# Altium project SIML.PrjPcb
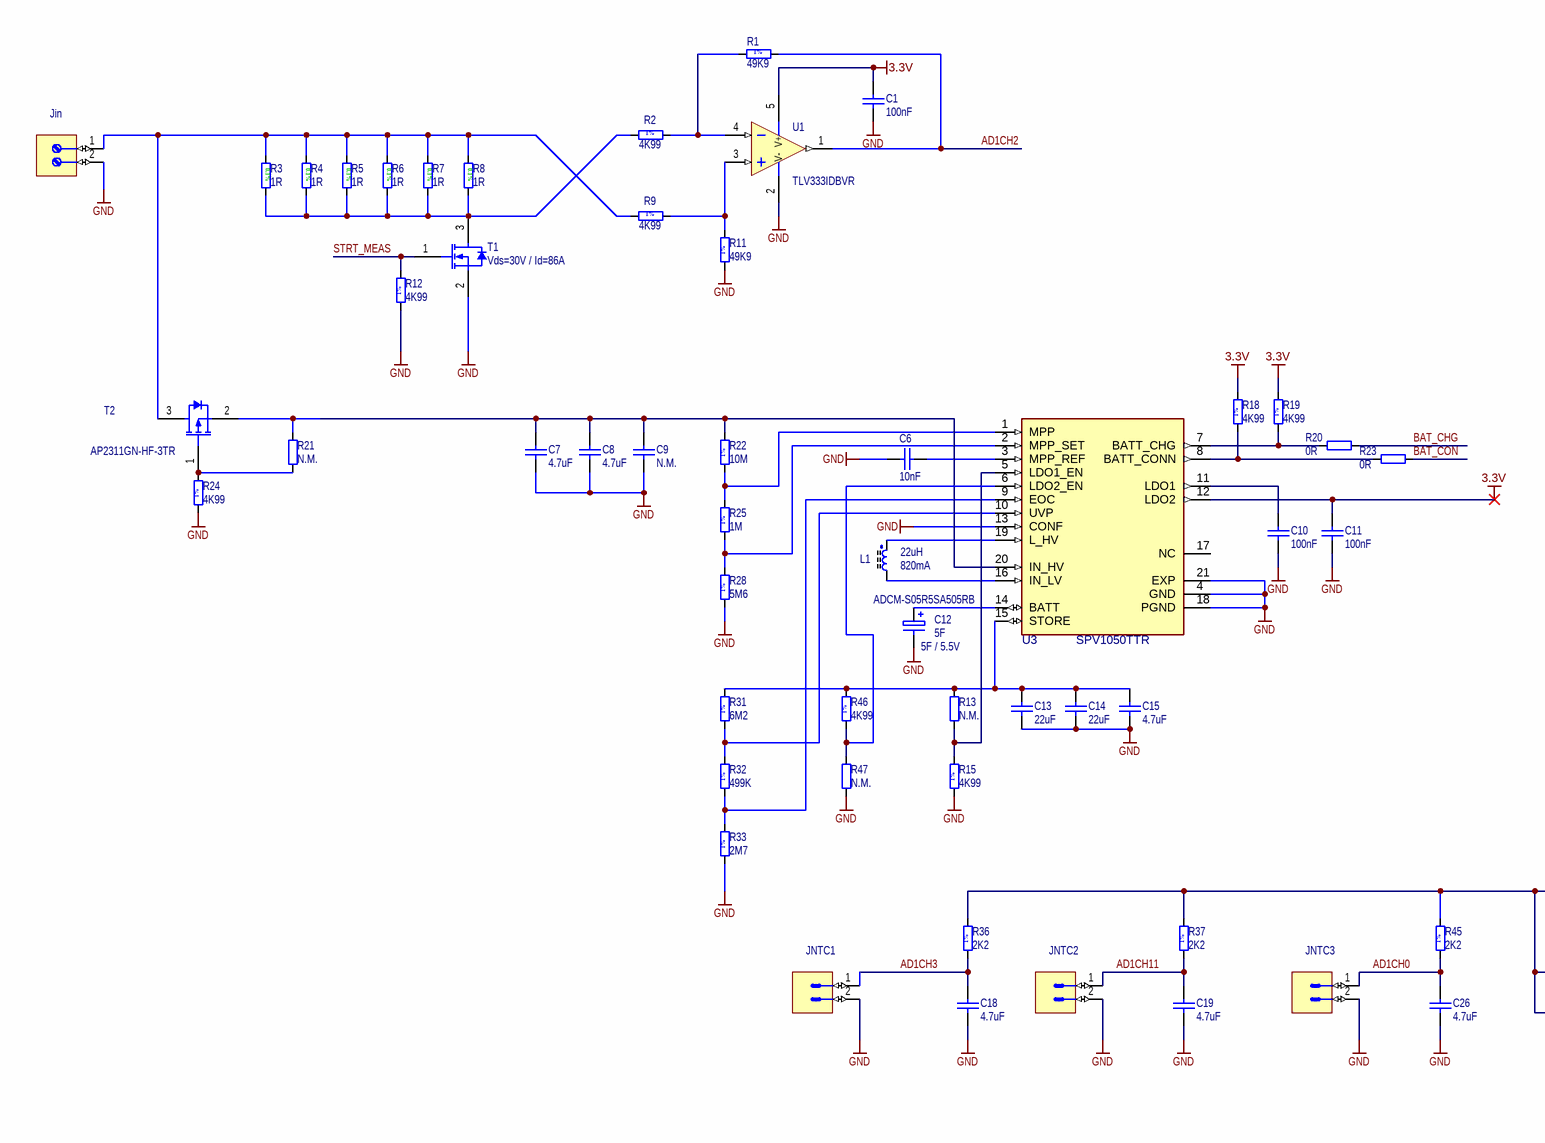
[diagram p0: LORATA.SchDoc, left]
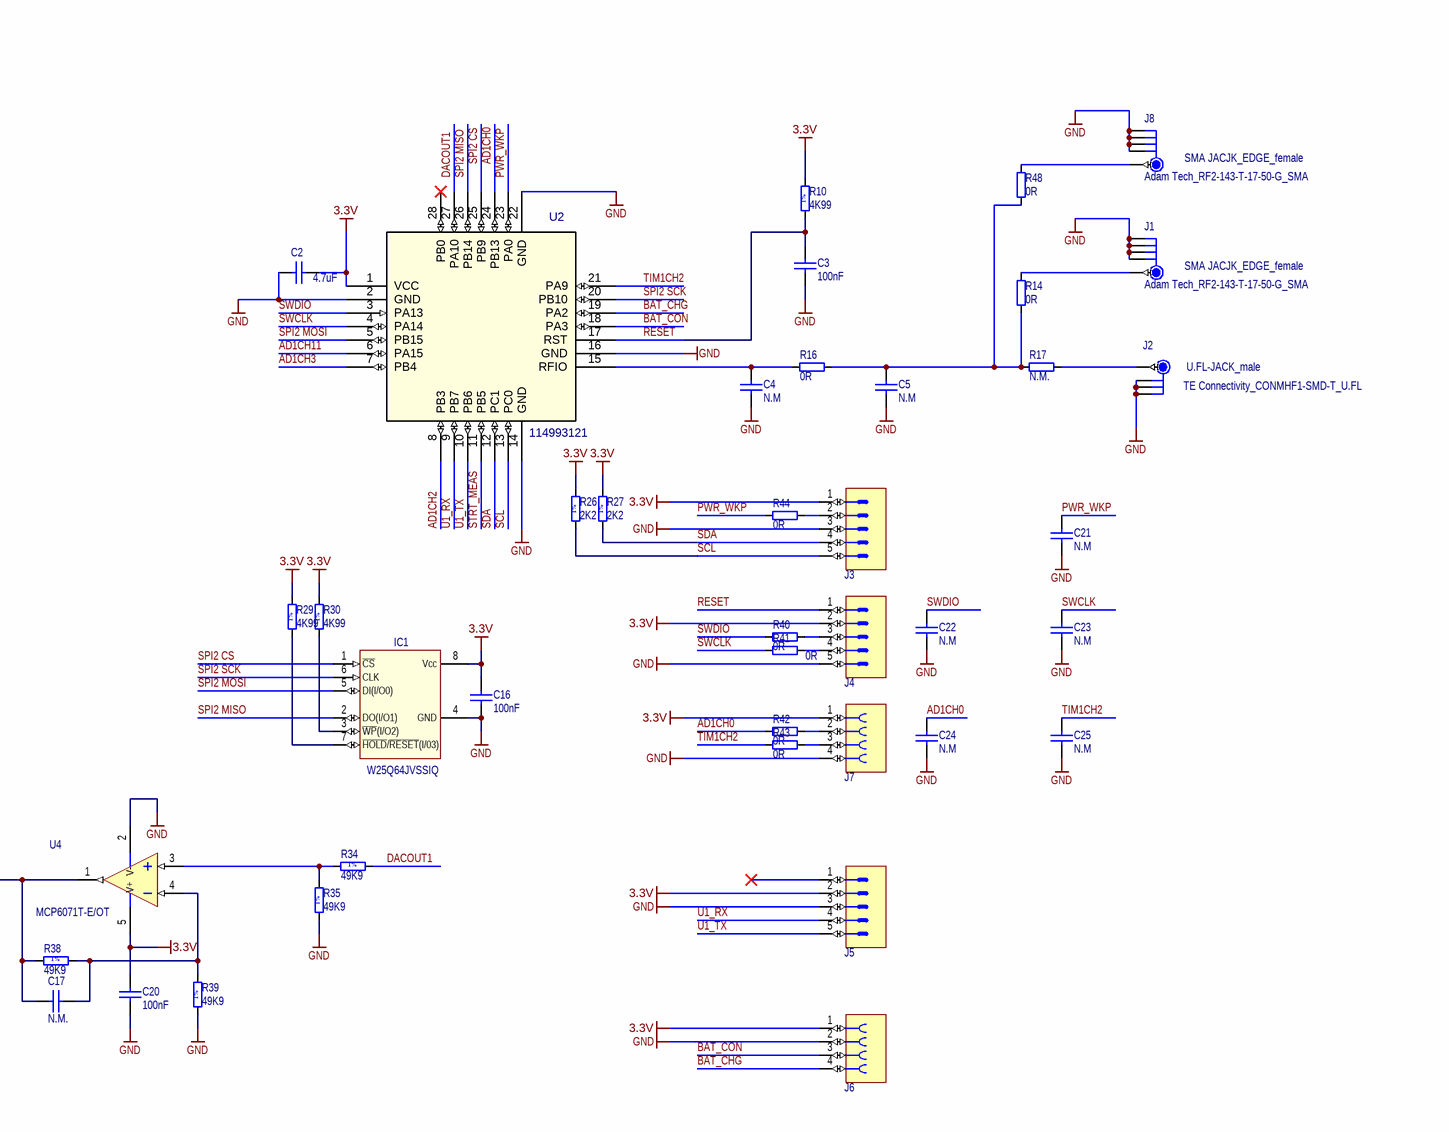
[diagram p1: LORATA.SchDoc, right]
1 sheet, 94 parts. Net scope: global (net labels, ports and power ports of the same name join across sheets).
Board file: SIML.PcbDoc

## Sheet LORATA.SchDoc
size A2; DocumentNumber: 2; SheetNumber: 2; SheetTotal: 4

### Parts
C1  100nF  [CAPC1608N]
C2  4.7uF  [CAPC3216N]
C3  100nF  [CAPC1608N]
C4  N.M  [CAPC1608N]
C5  N.M  [CAPC1608N]
C6  10nF  [CAPC1608N]
C7  4.7uF  [CAPC3216N]
C8  4.7uF  [CAPC3216N]
C9  N.M.  [CAPC2012N]
C10  100nF  [CAPC1608N]
C11  100nF  [CAPC1608N]
C12  5F  Comment_Ratings: 5F / 5.5V  Manufacturer Part Number: ADCM-S05R5SA505RB  [CAPR1530x1050X2050X2800]
C13  22uF  [CAPC3225N]
C14  22uF  [CAPC3225N]
C15  4.7uF  [CAPC3216N]
C16  100nF  [CAPC1608N]
C17  N.M.  [CAPC2012N]
C18  4.7uF  [CAPC3216N]
C19  4.7uF  [CAPC3216N]
C20  100nF  [CAPC1608N]
C21  N.M  [CAPC1608N]
C22  N.M  [CAPC1608N]
C23  N.M  [CAPC1608N]
C24  N.M  [CAPC1608N]
C25  N.M  [CAPC1608N]
C26  4.7uF  [CAPC3216N]
IC1  W25Q64JVSSIQ  [SOIC127P600-8N]
J1  SMA JACJK_EDGE_female  Part Number: Adam Tech_RF2-143-T-17-50-G_SMA  [Adam Tech_RF2-143-T-17-50-G]
J2  U.FL-JACK_male  Part Number: TE Connectivity_CONMHF1-SMD-T_U.FL  [LINX_CONMHF1-SMD-T]
J3  HEADER 1X5  [HDR1X5]  (value not drawn)
J4  HEADER 1X5  [HDR1X5]  (value not drawn)
J5  HEADER 1X5  [HDR1X5]  (value not drawn)
J6  Header Female  [HARWIN_M20-7820442]  (value not drawn)
J7  Header Female  [HARWIN_M20-7820442]  (value not drawn)
J8  SMA JACJK_EDGE_female  Part Number: Adam Tech_RF2-143-T-17-50-G_SMA  [Adam Tech_RF2-143-T-17-50-G]
Jin  DG381S  [DEGSON_DG381S-3.5-02P-14-00AH]  (value not drawn)
JNTC1  CI31 Series 2.54mm(.100")  [CVILUX_CI3102P1V00]  (value not drawn)
JNTC2  CI31 Series 2.54mm(.100")  [CVILUX_CI3102P1V00]  (value not drawn)
JNTC3  CI31 Series 2.54mm(.100")  [CVILUX_CI3102P1V00]  (value not drawn)
L1  22uH  Power: 820mA  [IND_Taiyo_NRS5024]
R1  49K9  [RESC1608N(0603)]
R2  4K99  [RESC2012N(0805)]
R3  1R  [RESC3216N(1206)]
R4  1R  [RESC3216N(1206)]
R5  1R  [RESC3216N(1206)]
R6  1R  [RESC3216N(1206)]
R7  1R  [RESC3216N(1206)]
R8  1R  [RESC3216N(1206)]
R9  4K99  [RESC2012N(0805)]
R10  4K99  [RESC2012N(0805)]
R11  49K9  [RESC1608N(0603)]
R12  4K99  [RESC2012N(0805)]
R13  N.M.  [RESC2012N(0805)]
R14  0R  [RESC1608N(0603)]
R15  4K99  [RESC2012N(0805)]
R16  0R  [RESC1608N(0603)]
R17  N.M.  [RESC2012N(0805)]
R18  4K99  [RESC2012N(0805)]
R19  4K99  [RESC2012N(0805)]
R20  0R  [RESC1608N(0603)]
R21  N.M.  [RESC2012N(0805)]
R22  10M  [RESC2012N(0805)]
R23  0R  [RESC1608N(0603)]
R24  4K99  [RESC2012N(0805)]
R25  1M  [RESC2012N(0805)]
R26  2K2  [RESC2012N(0805)]
R27  2K2  [RESC2012N(0805)]
R28  5M6  [RESC2012N(0805)]
R29  4K99  [RESC2012N(0805)]
R30  4K99  [RESC2012N(0805)]
R31  6M2  [RESC2012N(0805)]
R32  499K  [RESC2012N(0805)]
R33  2M7  [RESC2012N(0805)]
R34  49K9  [RESC1608N(0603)]
R35  49K9  [RESC1608N(0603)]
R36  2K2  [RESC2012N(0805)]
R37  2K2  [RESC2012N(0805)]
R38  49K9  [RESC1608N(0603)]
R39  49K9  [RESC1608N(0603)]
R40  0R  [RESC1608N(0603)]
R41  0R  [RESC1608N(0603)]
R42  0R  [RESC1608N(0603)]
R43  0R  [RESC1608N(0603)]
R44  0R  [RESC1608N(0603)]
R45  2K2  [RESC2012N(0805)]
R46  4K99  [RESC2012N(0805)]
R47  N.M.  [RESC2012N(0805)]
R48  0R  [RESC1608N(0603)]
T1  Comment_Ratings: Vds=30V / Id=86A  [TO228P991X239-3N-R546X521]  (hidden comment: IRLR8726PBF)
T2  AP2311GN-HF-3TR  [SOT95P240X130-3N]
U1  TLV333IDBVR  [SOT95P280X145-5N]
U2  114993121  [QFN_90687_SEE-L]
U3  SPV1050TTR  [QFN40P300X300X100-21N]
U4  MCP6071T-E/OT  [SOT95P280X145-5N]

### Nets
3.3V: C1.2 C2.2 C11.2 C16.2 C20.2 IC1.8(Vcc) J3.1 J4.2 J5.2 J6.1 J7.1 R10.2 R18.2 R19.2 R26.2 R27.2 R29.2 R30.2 U1.5(V+) U2.1(VCC) U3.12(LDO2) U4.5(V+)
GND: C1.1 C2.1 C3.1 C4.1 C5.1 C6.2 C7.1 C8.1 C9.1 C10.1 C11.1 C12.2 C13.1 C14.1 C15.1 C16.1 C18.1 C19.1 C20.1 C21.2 C22.2 C23.2 C24.2 C25.2 C26.1 IC1.4(GND) J1.2 J1.3 J1.4 J1.5 J2.2 J2.3 J2.4 J3.3 J4.5 J5.3 J6.2 J7.4 J8.2 J8.3 J8.4 J8.5 Jin.2 JNTC1.2 JNTC2.2 JNTC3.2 R11.1 R12.1 R15.1 R24.1 R28.1 R33.1 R35.1 R39.1 R47.1 T1.2(S) U1.2(V-) U2.2(GND) U2.14(GND) U2.16(GND) U2.22(GND) U3.4(GND) U3.13(CONF) U3.18(PGND) U3.21(EXP) U4.2(V-)
AD1CH0: C24.1 C26.2 JNTC3.1 R42.1 R45.1 U2.24(PB13)
AD1CH2: R1.2 U1.1(OUT) U2.8(PB3)
AD1CH3: C18.2 JNTC1.1 R36.1 U2.7(PB4)
AD1CH11: C19.2 JNTC2.1 R37.1 U2.6(PA15)
BAT_CHG: J6.4 R20.2 U2.19(PA2)
BAT_CON: J6.3 R23.2 U2.18(PA3)
DACOUT1: R34.2 U2.27(PA10)
PWR_WKP: C21.1 R44.1 U2.23(PA0)
RESET: C3.2 J4.1 R10.1 U2.17(RST)
SCL: J3.5 R26.1 U2.13(PC0)
SDA: J3.4 R27.1 U2.12(PC1)
SPI2 CS: IC1.1(~{CS}) U2.25(PB9)
SPI2 MISO: IC1.2(DO(I/O1)) U2.26(PB14)
SPI2 MOSI: IC1.5(DI(I/O0)) U2.5(PB15)
SPI2 SCK: IC1.6(CLK) U2.20(PB10)
STRT_MEAS: R12.2 T1.1(G) U2.11(PB5)
SWCLK: C23.1 R41.1 U2.4(PA14)
SWDIO: C22.1 R40.1 U2.3(PA13)
TIM1CH2: C25.1 R43.1 U2.21(PA9)
U1_RX: J5.4 U2.9(PB7)
U1_TX: J5.5 U2.10(PB6)
NetC4_2: C4.2 R16.1 U2.15(RFIO)
NetC5_2: C5.2 R14.1 R16.2 R17.1 R48.1
NetC6_1: C6.1 U3.3(MPP_REF)
NetC7_2: C7.2 C8.2 C9.2 R21.2 R22.2 T2.2(S) U3.20(IN_HV)
NetC10_2: C10.2 U3.11(LDO1)
NetC12_1: C12.1 U3.14(BATT)
NetC13_2: C13.2 C14.2 C15.2 R13.2 R31.2 R46.2 U3.15(STORE)
NetC17_1: C17.1 R38.1 R39.2 U4.4(-IN)
NetC17_2: C17.2 R36.2 R37.2 R38.2 R45.2 U4.1(OUT)
NetIC1_3: IC1.3(~{WP}(I/O2)) R30.1
NetIC1_7: IC1.7(~{HOLD}/~{RESET}(I/03)) R29.1
NetJ1_1: J1.1 R14.2
NetJ2_1: J2.1 R17.2
NetJ3_2: J3.2 R44.2
NetJ4_3: J4.3 R40.2
NetJ4_4: J4.4 R41.2
NetJ7_2: J7.2 R42.2
NetJ7_3: J7.3 R43.2
NetJ8_1: J8.1 R48.2
NetJin_1: Jin.1 R3.1 R4.1 R5.1 R6.1 R7.1 R8.1 R9.1 T2.3(D)
NetL1_1: L1.1 U3.19(L_HV)
NetL1_2: L1.2 U3.16(IN_LV)
NetR1_1: R1.1 R2.2 U1.4(-IN)
NetR2_1: R2.1 R3.2 R4.2 R5.2 R6.2 R7.2 R8.2 T1.3(D)
NetR9_2: R9.2 R11.2 U1.3(+IN)
NetR13_1: R13.1 R15.2 U3.5(LDO1_EN)
NetR18_1: R18.1 R23.1 U3.8(BATT_CONN)
NetR19_1: R19.1 R20.1 U3.7(BATT_CHG)
NetR21_1: R21.1 R24.2 T2.1(G)
NetR22_1: R22.1 R25.2 U3.1(MPP)
NetR25_1: R25.1 R28.2 U3.2(MPP_SET)
NetR31_1: R31.1 R32.2 U3.10(UVP)
NetR32_1: R32.1 R33.2 U3.9(EOC)
NetR34_1: R34.1 R35.2 U4.3(+IN)
NetR46_1: R46.1 R47.2 U3.6(LDO2_EN)

Not connected (* = marked no-connect by the designer): J5 1*; U2 28(PB0)*; U3 17(NC)

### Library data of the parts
C1 C3 C10 C11 C16 C20 = CC0603_100NF_50V_10%_X7R: Non-polarised capacitor; Part Description: SMD Multilayer Chip Ceramic Capacitor; Manufacturer: GENERIC; Manufacturer1 Part Number: C1608X7R1H104K080AA; Comment_Ratings: 100nF / 50V; Voltage: 50V; TC: X7R; Tolerance: ±10%; Table: Capacitors SMD; Elinvent_Num: 33-1002-02
C2 C7 C8 C15 C18 C19 C26 = CC1206_4.7UF_50V_10%_X7R: Non-polarised capacitor; Part Description: SMD Multilayer Chip Ceramic Capacitor; Manufacturer: GENERIC; Manufacturer1 Part Number: C3216X7R1H475K160AC; Voltage: 50V; TC: X7R; Tolerance: ±10%; Table: Capacitors SMD; Elinvent_Num: 33-1058-04; Comment_Ratings: 4.7uF / 50V
C4 C5 C21-C25 = CC0603_NO-VALUE: Non-polarised capacitor; Part Description: SMD Multilayer Chip Ceramic Capacitor; Manufacturer: GENERIC; Table: Capacitors SMD
C6 = CC0603_10NF_50V_10%_X7R: Non-polarised capacitor; Part Description: SMD Multilayer Chip Ceramic Capacitor; Manufacturer: GENERIC; Manufacturer1 Part Number: C1608X7R1H103K080AA; Comment_Ratings: 10nF / 50V; Voltage: 50V; TC: X7R; Tolerance: ±10%; Table: Capacitors SMD; Elinvent_Num: 33-1004-02
C9 C17 = CC0805_NO-VALUE: Non-polarised capacitor; Part Description: Reserved Footprint For 0805(2012) Chip Ceramic Capacitor; Manufacturer: Undefined; Mounted: No; Table: Capacitors SMD
C12 = CAER_5F_5.5V_0%+30%: Polarised capacitor; Part Description: 5 F (EDLC) Supercapacitor 5.5 V Radial 160mOhm @ 1kHz; Manufacturer: Abracon LLC; Voltage: 5.5V; Tolerance: 0%+30%; Table: Capacitors THD
C13 C14 = CC1210_22UF_16V_10%_X7R: Non-polarised capacitor; Part Description: SMD Multilayer Chip Ceramic Capacitor; Manufacturer: GENERIC; Manufacturer Part Number: CC1210_22UF_10V_10%_X7R; Manufacturer1 Part Number: C3225X7R1C226K250AC; Comment_Ratings: 22uF / 16V; Voltage: 16V; TC: X7R; Tolerance: ±10%; Table: Capacitors SMD; Elinvent_Num: 33-1005-05
IC1 = W25Q64JVSSIQ: FLASH - NOR Memory IC 64Mbit SPI - Quad I/O 133 MHz 8-SOIC; Manufacturer: Winbond Electronics; Table: Logic
J1 J8 = Adam Tech_RF2-143-T-17-50-G_SMA: Part Description: SMA Connector Jack, Female Socket 50 Ohms Board Edge, End Launch Solder; Table: Miscellaneous
J2 = TE Connectivity_CONMHF1-SMD-T_U.FL: Part Description: U.FL (UMCC) Connector Jack, Male Pin 50 Ohms Surface Mount Solder; Manufacturer: TE Connectivity Linx; Table: Miscellaneous
J3-J5 = HEADER 1 X 5_2.54MM: Connector 5 Male; Part Description: 5 Contacts - Pitch 2.54mm; Manufacturer Part Number: DO NOT MOUNT; Mounted: No; Table: Miscellaneous
J6 J7 = M20-7820442: Connector 4 Female; Part Description: 4 Contacts - 	Connector  Receptacle 4 Position 0.100" (2.54mm) Gold Through ole single row; Manufacturer: HARWIN; Elinvent_Num: 38-2064-01; Table: Miscellaneous
Jin = DEGSON_DG381S-3.5-02P-14-00AH: Terminal Block, 2 Positions, Screw Connection; Part Description: Plug component, Nominal current: 10 A, Nom. voltage: 250 V, Pitch:3.5 mm, Number of positions: 2, Connection type: Screw connection,45deg / Color: green; Manufacturer: DEGSON; Comment_Ratings: 300V / 10A / 16-26 AWG; Table: Miscellaneous
JNTC1-JNTC3 = CVILUX_CI3102P1V00: Connector 2 Male; Part Description: Connector PCB 2.54mm 2P 3A/250V; Manufacturer: CVILUX; Table: Miscellaneous
L1 = IND_22UH_20%_Taiyo-Yuden_NRS5024T220MMGJV: Inductor; Part Description: 22 µH Shielded Drum Core, Wirewound Inductor 820 mA 276mOhm Max Nonstandard; Manufacturer: Taiyo Yuden; Comment_Ratings: 22uH / 0.82A; Resistance: 0.276R; Tolerance: ±20%; Table: Inductors SMD
R1 R11 R34 R35 R38 R39 = R0603_49K9_1%_0.1W_100PPM: Resistor-1%; Part Description: General Purpose Thick Film Chip Resistor; Manufacturer: GENERIC; Manufacturer1 Part Number: RC0603FR-0749K9L; Comment_Ratings: 49K9 / 0.1W; Power: 0.1W; TC: ±100ppm/°C; Tolerance: ±1%; Table: Resistors SMD
R2 R9 R10 R12 R15 R18 R19 R24 R29 R30 R46 = R0805_4K99_1%_0.125W_100PPM: Resistor-1%; Part Description: General Purpose Thick Film Chip Resistor; Manufacturer: Vishay Dale; Manufacturer1 Part Number: CRCW08054K99FKEA; Comment_Ratings: 4K99 / 0.125W; Power: 0.125W; TC: ±100ppm/°C; Tolerance: ±1%; Table: Resistors SMD
R3-R8 = R1206_1R_0.5%_0.52W_25PPM: Resistor-0.1%; Part Description: 1 Ohms ±0.5% 0.52W Chip Resistor 1206 (3216 Metric) Anti-Sulfur, Automotive AEC-Q200, Moisture Resistant Thin Film; Manufacturer: YAGEO; Manufacturer Part Number: TNPW12061R00DEEA; Manufacturer1 Part Number: RES 1 OHM 0.5% 0.52W 1206; Comment_Ratings: 1R / 0.52W / 25PPM; Power: 0.25W; TC: ±25ppm/°C; Tolerance: ±0.5%; Table: Resistors SMD
R13 R17 R21 R47 = R0805_NO-VALUE: Resistor; Part Description: Reserved Footprint For a 0805 (2012) Chip Resistor; Manufacturer: Undefined; Mounted: No; Table: Resistors SMD
R14 R16 R20 R23 R40-R44 R48 = R0603_0R_JUMPER: Resistor; Part Description: 1A (0.05R Max DC Resistance) Zero Ohm Jumper; Manufacturer: GENERIC; Manufacturer1 Part Number: RC0603JR-070RL; Elinvent_Num: 36-1001-03; Comment_Ratings: 0R / 1A Max; Table: Resistors SMD
R22 = R0805_10M_1%_0.125W_100PPM: Resistor-1%; Part Description: General Purpose Thick Film Chip Resistor; Manufacturer: Vishay Dale; Manufacturer1 Part Number: CRCW080510M00FKEA; Comment_Ratings: 10M / 0.125W; Power: 0.125W; TC: ±100ppm/°C; Tolerance: ±1%; Table: Resistors SMD
R25 = R0805_1M_1%_0.125W_100PPM: Resistor-1%; Part Description: General Purpose Thick Film Chip Resistor; Manufacturer: Vishay Dale; Manufacturer1 Part Number: CRCW08051M00FKEA; Comment_Ratings: 1M / 0.125W; Power: 0.125W; TC: ±100ppm/°C; Tolerance: ±1%; Table: Resistors SMD
R26 R27 R36 R37 R45 = R0805_2K2_1%_0.125W_100PPM: Resistor-1%; Part Description: Commercial Thin Film Resistor, Surface Mount Chip; Manufacturer: GENERIC; Manufacturer1 Part Number: RC0805FR-072K2L; Elinvent_Num: 36-1031-05; Comment_Ratings: 2K2 / 0.125W; Power: 0.125W; TC: ±100ppm/°C; Tolerance: ±1%; Table: Resistors SMD
R28 = R0805_5M6_1%_0.125W_100PPM: Resistor-1%; Part Description: General Purpose Thick Film Chip Resistor; Manufacturer: Vishay Dale; Manufacturer1 Part Number: CRCW08055M60FKEA; Comment_Ratings: 5M6 / 0.125W; Power: 0.125W; TC: ±100ppm/°C; Tolerance: ±1%; Table: Resistors SMD
R31 = R0805_6M2_1%_0.125W_100PPM: Resistor-1%; Part Description: General Purpose Thick Film Chip Resistor; Manufacturer: Vishay Dale; Manufacturer1 Part Number: CRCW08056M20FKEA; Comment_Ratings: 6M2 / 0.125W; Power: 0.125W; TC: ±100ppm/°C; Tolerance: ±1%; Table: Resistors SMD
R32 = R0805_499K_1%_0.125W_100PPM: Resistor-1%; Part Description: Commercial Thin Film Resistor, Surface Mount Chip; Manufacturer: GENERIC; Manufacturer1 Part Number: RC0805FR-07499KL; Elinvent_Num: 36-1101-05; Comment_Ratings: 499K / 0.125W; Power: 0.125W; TC: ±100ppm/°C; Tolerance: ±1%; Table: Resistors SMD
R33 = R0805_2M7_1%_0.125W_100PPM: Resistor-1%; Part Description: General Purpose Thick Film Chip Resistor; Manufacturer: Vishay Dale; Manufacturer1 Part Number: CRCW08052M70FKEA; Comment_Ratings: 2M7 / 0.125W; Power: 0.125W; TC: ±100ppm/°C; Tolerance: ±1%; Table: Resistors SMD
T1 = IRLR8726PBF: N-channel FET transistor in SOT-23; Part Description: MOSFET N-CH 30V 86A DPAK; Manufacturer: INFINEON TECHNOLOGIES; Table: Transistors; Elinvent_Num: 40-1070-00
T2 = AP2311GN-HF-3TR: P-channel FET transistor in SOT-23; Part Description: PMOS 60V 1.8A 1.38W 250mOhm/10V; 300mOhm/4.5V; Manufacturer: ADVANCED POWER ELECTR. CO; Comment_Ratings: Vds=60V / Id=1.8A; Table: Transistors
U1 = TLV333IDBVR: Single Op Amp in SOT23/5; Part Description: Zero-Drift Amplifier 1 Circuit Rail-to-Rail SOT-23-5; Manufacturer: TEXAS INSTRUMENTS; Table: Operational Amplifiers
U2 = 114993121_RF_SEED: WIO-E5-LE WIRELESS MODULE (TAPE); Mfr_Name: BeagleBoard; Part Description: General ISM < 1GHz LoRaWAN Transceiver Module 868MHz, 915MHz Antenna Not Included Surface Mount; Manufacturer: Seeed Technology Co., Ltd; Table: PCB Modules
U3 = SPV1050TTR: Charger IC Multi-Chemistry 20-VFQFPN (3x3); Part Description: IC BATT CHG MULTI-CHEM 20VFQFPN; MF: STMicroelectronics; Table: Analog & Interface
U4 = MCP6071T-E/OT: Single Op Amp in SOT23/5; Part Description: OP AMP, 1.2MHz, 0.5V/uS, 150 uV, 5-SOT-23, Supply Voltage Range:1.8V to 6V; Manufacturer: Analog Devices; Table: Operational Amplifiers; Elinvent_Num: 31-5113-00

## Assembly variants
SIML: not fitted C4 C5 C9 C17 C21 C22 C23 C24 C25 J3 J4 J5 J6 J7 J8 R13 R17 R21 R47 R48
